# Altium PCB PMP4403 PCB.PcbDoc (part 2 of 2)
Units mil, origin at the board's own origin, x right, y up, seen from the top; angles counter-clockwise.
Board outline 2204 x 1635 mil, 2 copper layers (Top Layer, Bottom Layer), stack 62 mil thick; 78 components, 89 nets, 246 pads, 22 vias.
Unrouted connection lines stored in the file: 1.
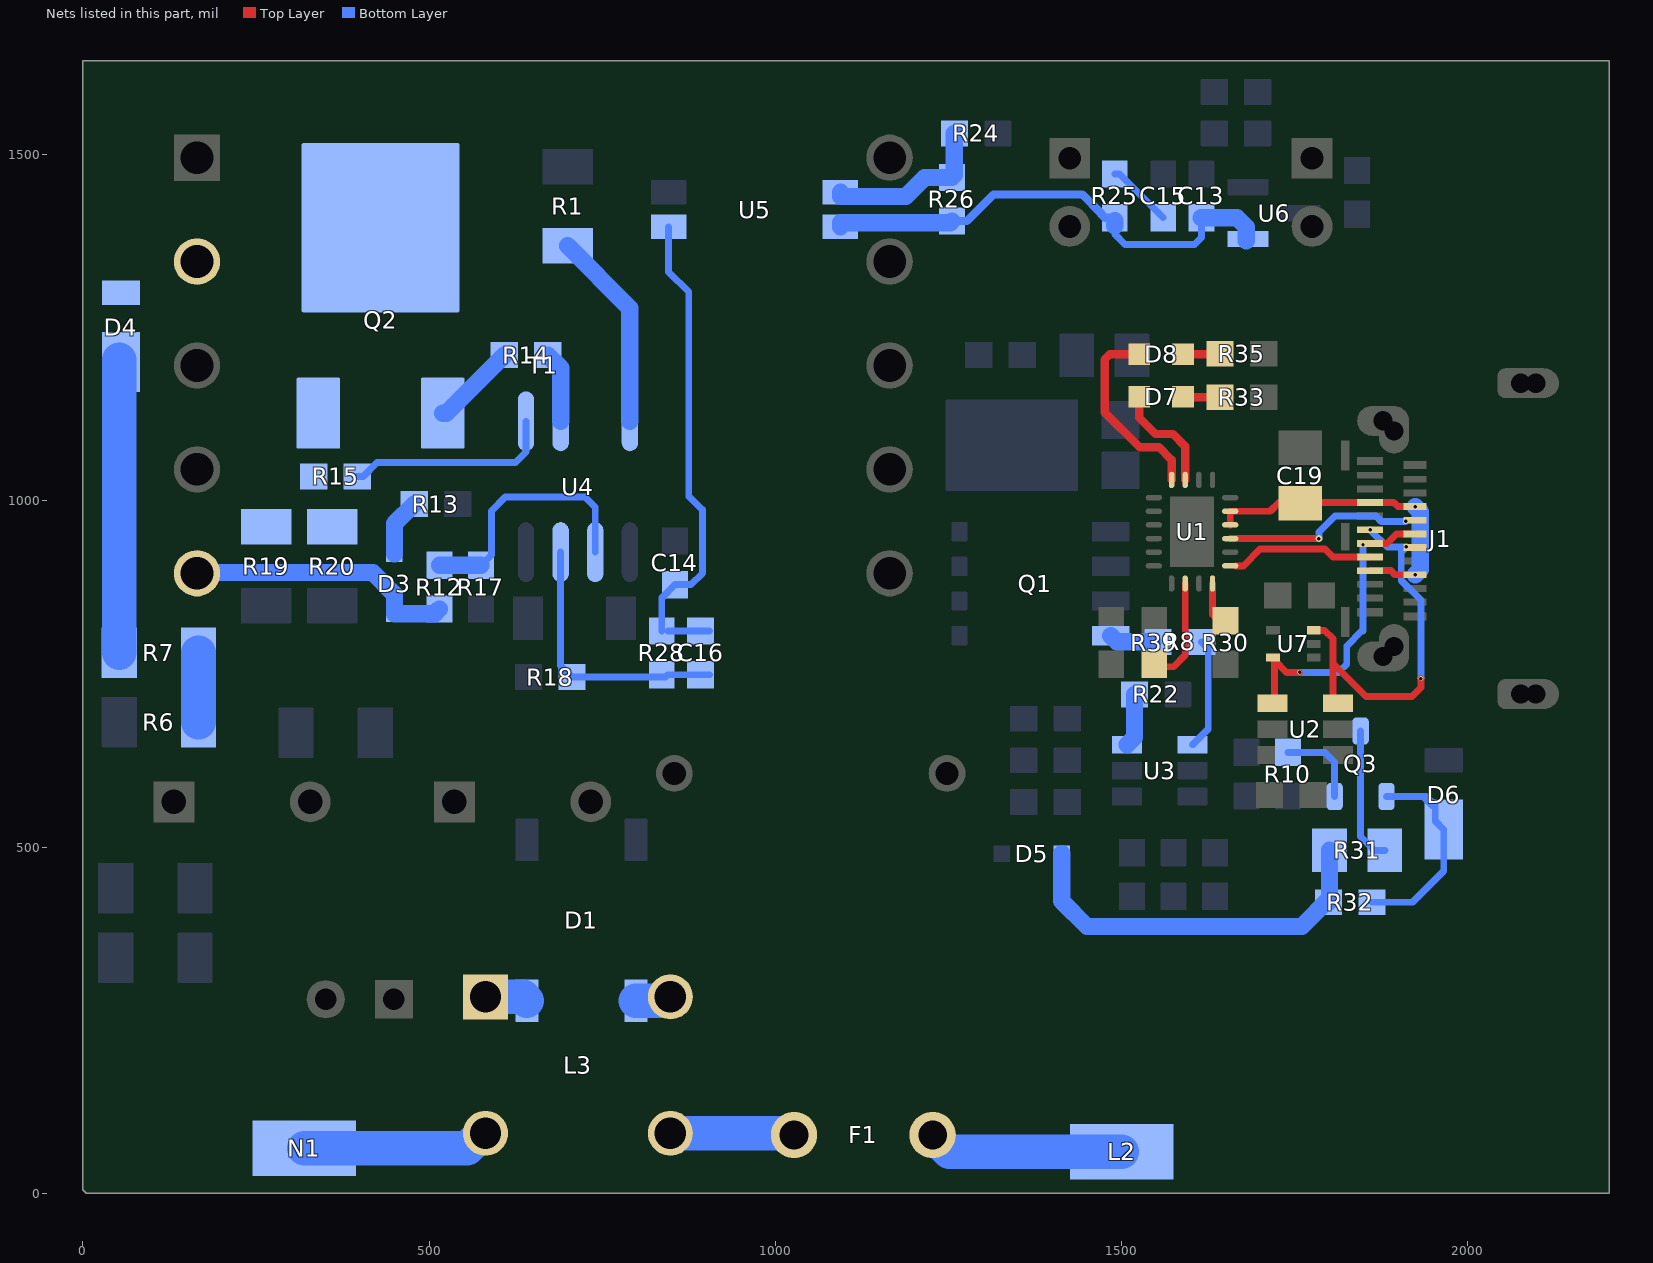
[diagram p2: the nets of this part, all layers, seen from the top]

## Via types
v1: diameter 10, hole 5, Top Layer to Bottom Layer, 8 vias
v2: diameter 7, hole 5, Top Layer to Bottom Layer, 8 vias
v3: diameter 19.68, hole 7.87, Top Layer to Bottom Layer, 6 vias

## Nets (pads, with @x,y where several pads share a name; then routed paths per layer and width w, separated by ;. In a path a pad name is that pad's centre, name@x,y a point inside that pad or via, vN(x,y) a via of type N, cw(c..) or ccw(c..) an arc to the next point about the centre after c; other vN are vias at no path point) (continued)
NetC13_2: C13.2 R25.1 R26.1 U5.2 U6.1 | length 706.8
  Bottom Layer w10: R25.1@1490.02,1397.17 1490.02,1385.42 1505.02,1370.42 1605.02,1370.42 1615.02,1380.42 C13.2@1615.02,1408.93
  Bottom Layer w12: R26.1@1255.02,1403.93 1276.52,1403.93 1315.02,1442.42 1443.19,1442.42 1470.54,1415.07 1470.54,1413.89 1475.51,1408.93 R25.1@1490.02,1408.93
  Bottom Layer w25: U5.2@1094.03,1395.42 1094.03,1401.39 1252.48,1401.39 R26.1@1255.02,1403.93 ; R25.1@1490.02,1397.17 R25.1@1490.02,1404.22 ; C13.2@1615.02,1408.93 1666.51,1408.93 1680.02,1395.42 U6.1@1680.02,1375.42
NetC14_2: C14.2 C16.1 R28.2 U5.3 | length 702.6
  Bottom Layer w10: R28.2@836.02,811.92 836.02,859.93 C14.2@855.02,878.93 878.52,878.93 895.02,895.42 895.02,987.42 894.02,987.42 875.02,1006.42 875.02,1301.41 846,1330.42 U5.3@846,1395.42 ; R28.2@845.02,811.92 C16.1@905.02,811.92
NetC15_2: C15.2 R25.2 | length 96.1
  Bottom Layer w10: R25.2@1490.02,1471.92 1497.02,1471.92 C15.2@1560.02,1408.93
NetC16_2: C16.2 R18.2 R28.1 U4.3 | length 387.3
  Bottom Layer w10: U4.3@690.02,925.93 690.02,761.92 R18.2@706.51,745.42 841.51,745.42 845.02,748.93 C16.2@905.02,748.93
NetC19_1: C19.1 J1.A4 J1.A9 J1.B4 J1.B9 U1.14 U1.15 | length 465.5
  Top Layer w10: U1.14@1656.79,965.26 U1.15@1656.79,984.63 ; U1.15@1656.79,984.95 1714.54,984.95 1727.18,997.59 J1.A9@1858.76,997.59 1892.85,997.59 1898.76,991.68 J1.B4@1923.72,991.68 ; J1.A4@1858.76,899.16 1888.76,899.16 1894.66,893.26 v2(1923.72,893.26)
  Bottom Layer w25: v2(1923.72,893.26) 1931.02,900.56 1931.02,984.42 v2(1924.02,991.42)
NetD1_3: D1.3 L3.4 | length 52.1
  Bottom Layer w50: D1.3@798.76,278.28 842.87,278.28 L3.4@848.52,283.92
NetD1_4: D1.4 L3.1 | length 62.1
  Bottom Layer w50: L3.1@581.52,283.92 635.63,283.92 D1.4@641.28,278.28
NetD3_1: D3.1 R13.2 | length 83.5
  Bottom Layer w25: D3.1@450.02,923.73 450.02,966.92 R13.2@478.52,995.42
NetD3_2: D3.2 R12.2 T1.5 | length 395
  Bottom Layer w25: T1.5@165.02,895.42 165.02,896.43 419.01,896.43 450.02,865.42 D3.2@450.02,837.11 508.2,837.11 R12.2@515.02,843.93
NetD4_1: D4.1 R7.1 | length 422.9
  Bottom Layer w50: R7.1@52.93,780.42 D4.1@52.93,1203.33
NetD4_2: D4.2 Q2.4 T1.2
NetD5_1: D5.1 R31.2 R32.2 | length 562.4
  Bottom Layer w25: D5.1@1413.32,490.42 1413.32,422.11 1450.02,385.42 1760.02,385.42 R32.2@1800.02,425.42 ; R32.2@1798.52,420.42 1800.02,421.92 R32.2@1800.02,425.42 ; R31.2@1800.02,495.42 R32.2@1800.02,425.42
NetD6_1: D6.1 Q3.1 R32.1 | length 321
  Bottom Layer w10: R32.1@1861.51,420.42 1920.21,420.42 1965.02,465.22 D6.1@1965.02,525.22 1952.77,537.47 D6.1@1952.77,560.42 ; Q3.1@1882.42,573.18 1935.02,573.18 ; 1935.02,573.18 1940.02,573.18 D6.1@1952.77,560.42 ; 1935.02,573.18 1947.77,560.42 D6.1@1952.77,560.42
NetD7_1: D7.1 U1.19 | length 162.3
  Top Layer w12: D7.1@1525.52,1150.42 1525.52,1119.92 1549.02,1096.42 1574.02,1096.42 1591.83,1078.61 1591.83,1056.42 U1.19@1591.83,1030.22
NetD7_2: D7.2 R33.1 | length 54
  Top Layer w12: D7.2@1588.51,1150.42 1589.31,1149.63 R33.1@1642.17,1149.63
NetD8_1: D8.1 U1.20 | length 283.3
  Top Layer w12: D8.1@1525.52,1211.69 1483.29,1211.69 1475.52,1203.92 1475.52,1127.92 1526.02,1077.42 1554.02,1077.42 1572.14,1059.3 U1.20@1572.14,1030.22
NetD8_2: D8.2 R35.1 | length 54
  Top Layer w12: D8.2@1588.51,1211.69 1641.44,1211.69 R35.1@1642.17,1212.42
NetF1_1: F1.1 L3.3 | length 181.7
  Bottom Layer w50: L3.3@848.52,86.92 1024.52,86.92 F1.1@1027.02,84.42 ; L3.3@848.52,91.92 L3.3@850.02,90.42
NetF1_2: F1.2 L2.1 | length 282.9
  Bottom Layer w50: F1.2@1227.02,84.42 1251.02,60.42 L2.1@1500.02,60.42
NetJ1_A5: J1.A5 U1.11 | length 208.5
  Top Layer w10: U1.11@1665.39,905.89 1665.39,906.21 1675.8,906.21 1700.02,930.42 1793.8,930.42 1805.37,918.85 J1.A5@1858.76,918.85
NetJ1_A6: J1.A6 J1.B6 U2.1 U7.5 | length 433.3
  Top Layer w10: U2.1@1717.77,707.82 1720.49,710.54 1720.49,769.95 1738.02,752.42 v2(1757.02,752.42) ; J1.A6@1858.76,938.53 1883.13,938.53 1896.91,952.31 J1.B6@1923.72,952.31
  Bottom Layer w10: v2(1757.02,752.42) 1813.02,752.42 ; 1814.02,753.42 1825.06,764.46 1825.06,790.41 1846.53,811.88 1848.47,811.88 v2(1848.47,936.88) v2@1849.02,937.42
NetJ1_A7: J1.A7 J1.B7 U2.6 U7.3 | length 574.5
  Top Layer w10: U7.3@1777.54,813.11 1793.02,813.11 1805.02,801.11 1805.02,765.42 ; U2.6@1797.26,707.82 1805.02,715.58 1805.02,765.42 ; v2(1911.02,933.42) 1911.81,932.63 J1.B7@1923.72,932.63 ; v2(1932.02,743.42) 1932.02,730.42 1919.02,717.42 1853.02,717.42 1805.02,765.42
  Bottom Layer w10: v1(1858.76,958.22) 1883.55,933.42 v2(1911.02,933.42) 1903.72,926.12 1903.72,884.97 1932.02,856.67 v2(1932.02,743.42)
NetJ1_B5: J1.B5 U1.13 | length 275.9
  Top Layer w10: U1.13@1656.79,945.58 v1(1784.86,945.58) v1@1785.02,945.42
  Bottom Layer w10: v1(1784.86,945.58) 1784.86,955.26 1807.81,978.22 1867.04,978.22 1874.84,970.42 v2(1910.02,970.42)
NetL3_2: L3.2 N1.1 | length 272.5
  Bottom Layer w50: N1.1@320.02,65.42 555.02,65.42 L3.2@581.52,91.92
NetQ1_4: Q1.4 R8.1 | length 71.9
  Bottom Layer w10: R8.1@1545.02,796.42 R8.1@1552.52,796.42
  Bottom Layer w25: Q1.4@1484.32,805.42 1493.32,796.42 R8.1@1545.02,796.42
NetQ2_1: Q2.1 R14.2 | length 123.5
  Bottom Layer w25: Q2.1@519.78,1126.56 524.66,1126.56 R14.2@608.52,1210.42
NetQ2_3: Q2.3 R15.2 R19.2 R20.2
NetQ3_2: Q3.2 R10.2 | length 123.1
  Bottom Layer w10: R10.2@1740.02,636.92 1793.52,636.92 1807.61,622.82 Q3.2@1807.61,573.18
NetQ3_3: Q3.3 R31.1 | length 195.5
  Bottom Layer w10: Q3.3@1845.02,667.67 1845.02,515.42 1865.02,495.42 R31.1@1880.02,495.42
NetR1_1: R1.1 U4.8 | length 290.7
  Bottom Layer w25: R1.1@700.02,1368.33 790.02,1278.33 U4.8@790.02,1114.91
NetR6_1: R6.1 R7.2 | length 100
  Bottom Layer w50: R6.1@167.1,680.42 R7.2@167.1,780.42
NetR8_2: R8.2 U3.4 | length 162
  Bottom Layer w10: U3.4@1602.26,647.82 1625.02,670.58 1625.02,786.92 R8.2@1615.51,796.42
NetR12_1: R12.1 R17.2 U4.2 | length 373.7
  Bottom Layer w10: R17.2@575.02,906.92 590.02,921.92 590.02,985.42 610.02,1005.42 725.02,1005.42 740.02,990.42 U4.2@740.02,925.93
  Bottom Layer w25: R12.1@515.02,906.92 R17.2@575.02,906.92
NetR14_1: R14.1 U4.6 | length 103.2
  Bottom Layer w25: R14.1@671.51,1210.42 690.02,1191.92 U4.6@690.02,1114.91
NetR15_1: R15.1 U4.5 | length 302.5
  Bottom Layer w10: R15.1@396.51,1035.42 405.02,1035.42 425.02,1055.42 625.02,1055.42 640.02,1070.42 U4.5@640.02,1114.91
NetR22_2: R22.2 U3.3 | length 77.1
  Bottom Layer w25: U3.3@1507.77,647.82 1518.52,658.57 R22.2@1518.52,720.42
NetR24_1: R24.1 R26.2 U5.1 | length 241.8
  Bottom Layer w10: R26.2@1255.02,1466.92 R26.2@1255.02,1470.42
  Bottom Layer w25: U5.1@1094.03,1445.42 1094.03,1439.46 1188.2,1439.46 1215.66,1466.92 R26.2@1255.02,1466.92 ; R26.2@1258.52,1470.42 R24.1@1258.52,1530.42
NetR30_2: R30.2 U1.10 | length 57.4
  Top Layer w10: U1.10@1631.2,880.62 1631.2,835.74 R30.2@1640.02,826.92
NetR39_1: R39.1 U1.8 | length 156.6
  Top Layer w10: R39.1@1547.07,763.93 1550.57,760.42 1575.02,760.42 1591.83,777.23 U1.8@1591.83,880.62
PWRGND: 
pads on no net: J1.A2 J1.A3 J1.A8 J1.A10 J1.A11 J1.B2 J1.B3 J1.B8 J1.B10 J1.B11 T1.3 T1.6 U1.1 U1.16 U1.17 U1.18 U2.3 U2.4 U7.2

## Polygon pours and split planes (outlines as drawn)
GND on Bottom Layer "Top Layer-No Net" (solid, remove dead copper, pour order 19): 1447.31,831.45 1450.02,834.15 1450.02,1165.42 1470.02,1185.42 1470.02,1243.42 1463.02,1250.42 1395.02,1250.42 1340.02,1250.42 1340.02,1305.42 1340.02,1405.42 1340.02,1410.42 1350.02,1420.42 1445.02,1420.42 1450.02,1420.42 1460.02,1410.42 1465.02,1405.42 1465.02,1370.42 1465.02,1365.42 1730.02,1365.42 1730.02,1410.42 1730.02,1415.42 1735.02,1420.42 1760.02,1445.42 2180.02,1445.42 2190.02,1445.42 2215.02,1420.42 2215.02,637.42 2168.02,590.42 1688.34,590.42 1640.02,638.74 1640.02,830.42 1455.02,830.42
NetC7_2 on Bottom Layer "Top Layer-No Net" (solid, remove dead copper, pour order 18): 1120.02,1015.42 1120.02,1250.42 1120.02,1255.42 1130.02,1265.42 1135.02,1270.42 1305.02,1270.42 1315.02,1270.42 1325.02,1260.42 1330.02,1255.42 1330.02,1175.42 1330.02,1170.42 1340.02,1160.42 1445.02,1160.42 1450.02,1155.42 1455.02,1150.42 1455.02,785.42 1455.02,780.42 1450.02,775.42 1445.02,770.42 1170.02,770.42 1145.02,770.42 1120.02,795.42
NetD4_2 on Bottom Layer "Top Layer-No Net" (solid, remove dead copper, pour order 13): 20.02,1270.42 20.02,1415.42 20.02,1420.42 30.02,1430.42 35.02,1435.42 240.02,1435.42 255.02,1450.42 265.02,1460.42 265.02,1535.42 280.02,1550.42 285.02,1555.42 570.02,1555.42 575.02,1550.42 575.02,1300.42 575.02,1280.42 555.02,1260.42 35.02,1260.42
NetQ2_3 on Bottom Layer "Top Layer-No Net" (solid, remove dead copper, pour order 12): 220.02,925.42 220.02,1130.42 220.02,1140.42 220.02,1195.42 375.02,1195.42 390.02,1195.42 390.02,1180.42 390.02,1080.42 390.02,1075.42 380.02,1065.42 370.02,1065.42 365.02,1060.42 365.02,1010.42 365.02,1005.42 370.02,1000.42 410.02,1000.42 415.02,995.42 415.02,920.42 415.02,915.42 410.02,910.42 405.02,905.42 235.02,905.42
GND on Top Layer "Top Layer-No Net" (solid, remove dead copper, pour order 16): 1712.02,1047.42 1712.02,1117.42 1712.02,1118.42 1714.02,1120.42 1716.02,1122.42 1762.02,1122.42 1797.02,1157.42 1917.02,1157.42 1933.02,1157.42 1945.02,1145.42 1945.02,1053.42 1945.02,1048.42 1942.02,1045.42 1941.02,1046.42 1840.02,1046.42 1840.02,1045.42 1831.02,1036.42 1720.02,1036.42
NetC19_1 on Top Layer "Top Layer-No Net" (solid, remove dead copper, pour order 22): 1640.02,965.42 1640.02,985.42 1650.02,995.42 1680.02,995.42 1690.02,1005.42 1700.02,1015.42 1713.02,1028.42 1771.02,1028.42 1817.02,1028.42 1830.02,1015.42 1840.02,1005.42 1840.02,995.42 1800.02,955.42 1710.02,955.42 1650.02,955.42
GND on Top Layer "Top Layer-No Net" (solid, remove dead copper, pour order 21): 1210.02,535.42 1210.02,765.42 1210.02,770.42 1230.02,790.42 1465.02,790.42 1480.02,790.42 2140.89,790.42 2153.02,781.12 2153.02,579.42 2153.02,430.38 2142.32,420.42 2075.02,420.42 1218.02,420.42 1210.02,428.42
NetC4_1 on Top Layer "Top Layer-No Net" (solid, remove dead copper, pour order 20): 1532.79,795.42 1580.02,795.42 1585.02,800.42 1585.02,895.42 1580.02,900.42 1570.02,900.42 1565.02,905.42 1560.02,910.42 1560.02,990.42 1461.02,1089.43 1461.02,1232.42 1477.02,1248.42 1673.02,1248.42 1673.02,1124.42 1751.02,1124.42 1751.02,1248.42 1928.02,1248.42 1965.02,1285.42 1965.02,1340.42 1965.02,1592.42 1937.02,1620.42 1650.02,1620.42 1142.02,1620.42 1130.02,1608.42 1130.02,1260.42 1142.02,1248.42 1205.02,1248.42 1210.02,1243.42 1210.02,1223.99 1210.02,795.42
GND on Top Layer "Top Layer-No Net" (solid, remove dead copper, pour order 15): 115.02,715.42 115.02,1105.42 125.02,1115.42 235.02,1115.42 260.02,1115.42 275.02,1130.42 290.02,1145.42 290.02,1410.42 290.02,1420.42 330.02,1460.42 335.02,1465.42 760.02,1465.42 854.02,1465.42 895.02,1424.42 895.02,555.42 895.02,468.42 867.02,440.42 325.02,440.42 280.02,440.42 265.02,455.42 265.02,465.42 265.02,640.42 265.02,645.42 240.02,670.42 170.02,670.42 160.02,670.42
NetC1_1 on Top Layer "Top Layer-No Net" (solid, remove dead copper, pour order 14): 25.02,490.42 20.02,495.42 20.02,1550.42 220.02,1550.42 225.02,1545.42 225.02,1455.42 225.02,1450.42 215.02,1440.42 210.02,1435.42 115.02,1435.42 100.02,1435.42 85.02,1420.42 75.02,1410.42 75.02,650.42 75.02,640.42 105.02,610.42 175.02,610.42 185.02,600.42 185.02,490.42 185.02,485.42 175.02,475.42 45.02,475.42
GND on Top Layer "Top Layer-No Net" (solid, remove dead copper, pour order 17): 1839.02,745.42 1811.02,773.42 1811.02,775.42 1811.02,841.42 1819.02,849.42 1823.48,853.89 1923.72,853.89 1937.55,853.89 1945.02,846.42 1949.47,841.97 1949.47,758.61 1949.47,738.87 1941.02,730.42 1940.02,731.42 1852.02,731.42

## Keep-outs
Keep-Out Layer:
  the board outline again, w10
  text ".Layer_Name" at 577,-858.49 h60

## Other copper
Top Layer:
  text ".Layer_Name" at 577,-858.49 h60
Bottom Layer:
  text ".Layer_Name" at 577,-858.49 h60

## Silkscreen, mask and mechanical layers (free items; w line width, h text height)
Top Overlay:
  text "PMP4403_RevA" at 1427.02,187.42 h60
  text ".Layer_Name" at 577,-858.49 h60
Bottom Overlay:
  text ".Layer_Name" at 577,-858.49 h60
Top Paste:
  text ".Layer_Name" at 577,-858.49 h60
Bottom Paste:
  text ".Layer_Name" at 577,-858.49 h60
Top Solder:
  text ".Layer_Name" at 577,-858.49 h60
  text ".Layer_Name" at 577,-858.49 h60
Bottom Solder:
  text ".Layer_Name" at 577,-858.49 h60
Drill Guide:
  text ".Layer_Name" at 577,-858.49 h60
M1 Board Outline:
  text ".Layer_Name" at 577,-858.49 h60
M2 Board Dimensions:
  rectangle: 125,-400 500,-275
  rectangle: 0,-275 125,-150
  lines w7: 0,-275 1000,-275 ; 0,-150 0,-400 1000,-400 1000,-150 ; 125,-400 125,-150 ; 250,-400 250,-150 ; 500,-400 500,-150 ; 750,-400 750,-150
  text ".Layer_Name" at 577,-858.49 h60
M3 3D STEP Top:
  text ".Layer_Name" at 577,-858.49 h60
M4 3D STEP Bottom:
  text ".Layer_Name" at 577,-858.49 h60
M5 Assembly Top:
  lines w10: -292,-930.17 6308,-930.17 ; -292,-726.83 6310,-726.83 ; -292,-523.5 -292,-1133.5 3713,-1133.5 6310,-1133.5 6310,-523.5 -291.5,-523.5 -291.5,-1133.5 1284,-1133.5 ; 2173,-1133.5 2173,-523.5 ; 3440,-726.83 3440,-523.5 ; 4280,-726.83 4280,-523.5 ; 4902,-1140 4902,-937.17
  text "COMPONENTS MARKED 'DNP' SHOULD NOT BE POPULATED." at 1153.5,-318.5 h60
  text "ASSEMBLY VARIANT:" at 1153,-434 h60
  text ".VariantName" at 2189,-434 h60
  text "PCB VIEWED FROM TOP SIDE" at -228.5,-655.67 h60
  text "BOARD #:" at 2248,-655.67 h60
  text ".PRJ_Number" at 2793.5,-655.67 h60
  text "REV:" at 3638,-655.67 h60
  text ".PCB_Rev" at 3929.5,-655.67 h60
  text "SVN REV:" at 4476,-655.67 h60
  text ".VersionControl_RevNumber" at 4982,-655.67 h60
  text "TID #:" at 2248,-859 h60
  text ".TID" at 2793.5,-859 h60
  text "PLOT NAME =" at -228.5,-1064.34 h60
  text ".plot_File_Name" at 577,-1064.34 h60
  text "GENERATED    :" at 2250,-1064.34 h60
  text ".Print_Date" at 3119.5,-1064.34 h60
  text ".Print_Time" at 3848.5,-1064.34 h60
  text "TEXAS INSTRUMENTS" at 5113,-1064.34 h60
M6 Assembly Bottom:
  lines w10: -292.5,-727.33 6309.5,-727.33 ; -290.5,-930.67 6309.5,-930.67 ; 1115.5,-1140.5 1115.5,-937.67 ; 1737.5,-727.33 1737.5,-524 ; 2577.5,-727.33 2577.5,-524 ; 3844.5,-1134 3844.5,-524 ; 4733.5,-1134 6309,-1134 6309,-524 -292.5,-524 -292.5,-1134 2304.5,-1134 6309.5,-1134 6309.5,-524
  text "COMPONENTS MARKED 'DNP' SHOULD NOT BE POPULATED." at 6102,-318 h60
  text ".VariantName" at 5058,-434 h60
  text "ASSEMBLY VARIANT:" at 6097,-434 h60
  text ".VersionControl_RevNumber" at 1035.5,-656.17 h60
  text "SVN REV:" at 1541.5,-656.17 h60
  text ".PCB_Rev" at 2088,-656.17 h60
  text "REV:" at 2379.5,-656.17 h60
  text ".PRJ_Number" at 3224,-656.17 h60
  text "BOARD #:" at 3769.5,-656.17 h60
  text "PCB VIEWED FROM BOTTOM SIDE" at 6246,-656.17 h60
  text ".TID" at 3224,-859.5 h60
  text "TID #:" at 3769.5,-859.5 h60
  text "TEXAS INSTRUMENTS" at 904.5,-1064.84 h60
  text ".Print_Time" at 2169,-1064.84 h60
  text ".Print_Date" at 2898,-1064.84 h60
  text "GENERATED    :" at 3767.5,-1064.84 h60
  text ".plot_File_Name" at 5440.5,-1064.84 h60
  text "PLOT NAME =" at 6246,-1064.84 h60
M9 Title Sheet:
  drawing of 57 lines, arcs and shapes, not listed
  text "1" at 739.84,8036.5 h70
  text "2" at 3235.5,8036.5 h70
  text "3" at 5724.84,8036.5 h70
  text "4" at 8231.51,8036.5 h70
  text "5" at 10730.5,8036.5 h70
  text "6" at 13235.5,8036.5 h70
  text "A" at -416.5,6893.5 h70
  text "A" at 14383.5,6893.5 h70
  text "B" at -416.5,4513.5 h70
  text "B" at 14383.5,4513.5 h70
  text "C" at -416.5,2138.5 h70
  text "C" at 14383.5,2138.5 h70
  text "PROJECT TITLE:" at 11343.5,277.5 h45
  text ".PRJ_Title" at 11393.5,144.17 h70
  text "DESIGNED FOR:" at 11343.5,-23.5 h45
  text ".PRJ_Customer" at 11393.5,-163.5 h70
  text "D" at -416.5,-231.5 h70
  text "D" at 14383.5,-231.5 h70
  text "FILE NAME:" at 11343.5,-323.5 h45
  text ".PCB_File_Name_No_Path" at 11393.5,-443.5 h70
  text "Texas Instruments (TI) and/or its licensors do not warrant the accuracy or completeness of this specification" at 6374,-605.34 h45
  text "ENGINEER:" at 11343.5,-613.5 h45
  text "LAYOUT BY:" at 12848.5,-613.5 h45
  text "or any information contained therein. TI and/or its licensors do not warrant that this design will meet" at 6329.01,-718 h45
  text ".PRJ_Engineer" at 11393.5,-768.49 h70
  text ".PCB_Layout" at 12899,-768.49 h70
  text "the specifications, will be suitable for your application or fit for any particular purpose, or will operate in" at 6329.01,-830.67 h45
  text ".Layer_Name" at 577,-858.49 h60
  text "ALTIUM DESIGNER VERSION:" at 12848.5,-923.5 h45
  text "an implementation. TI and/or its licensors do not warrant that the design is production worthy. You should" at 6329.01,-943.33 h45
  text "completely validate and test your design implementation to confirm the system functionality for your application." at 6374,-1056 h45
  text ".print_Scale" at 11393.5,-1056.83 h70
  text ".Application_BuildNumber" at 12899,-1056.83 h70
  text "1" at 739.84,-1263.5 h70
  text "2" at 3235.5,-1263.5 h70
  text "3" at 5724.84,-1263.5 h70
  text "4" at 8231.51,-1263.5 h70
  text "5" at 10730.5,-1263.5 h70
  text "6" at 13235.5,-1263.5 h70
M10 Fab Notes:
  drawing of 173 lines, arcs and shapes, not listed
  text "DESIGN INFORMATION" at 12377.02,6201 h60
  text "MIN. TRACK WIDTH:" at 11732.46,6021 h60
  text "8" at 12828.7,6021 h60
  text "MIL" at 12983.46,6021 h60
  text "MIN. CLEARANCE:" at 11732.46,5889 h60
  text "0.2" at 12768.7,5889 h60
  text "mm" at 12983.46,5889 h60
  text "MIN. VIA PAD SIZE:" at 11732.46,5757 h60
  text "24" at 12798.71,5757 h60
  text "MIL" at 12983.46,5757 h60
  text "0.05mm (2MIL)" at 12427.46,5615.29 h60
  text "MINIMUM ANNULAR RING" at 11403.23,5611 h60
  text "EXTERNAL" at 13135.46,5611 h60
  text "PER" at 11603.23,5493 h60
  text "IPC-D-275 CLASS 2 LEVEL C" at 11823.23,5493 h60
  text "MIL, HOLES" at 13311.46,5380.71 h60
  text "+/-" at 12919,5380 h60
  text "+/-" at 13773,5380 h60
  text "REGISTRATION TOLERANCES:" at 11403.23,5375 h60
  text "METAL" at 12603,5375 h60
  text "5" at 13179.2,5375 h60
  text "3" at 14012.2,5375 h60
  text "MIL" at 14128.46,5375 h60
  text "+/-" at 13773,5262 h60
  text "HOLE SIZE TOLERANCE (UNLESS OTHERWISE SPECIFIED):" at 11403.23,5257 h60
  text "3" at 14012.2,5257 h60
  text "MIL" at 14128.46,5257 h60
  text "MATERIAL:" at 11328.46,5047.54 h60
  text "FR-4 High Tg" at 12314.9,4907.21 h60
  text "FR-408" at 11749.46,4898.64 h60
  text "OTHER" at 13237.46,4898.64 h60
  text "X" at 12160,4895 h60
  text "62 MIL (1.6mm) +/-10%" at 12069.56,4735.92 h60
  text "THICKNESS:" at 11403.23,4731.64 h60
  text "X" at 11941.4,4731.64 h60
  text "OTHER" at 13354.46,4731.64 h60
  text "TOLERANCE:" at 11403.23,4573.64 h60
  text "X" at 12242.53,4573.64 h60
  text "ANSI IPC-6012 TYPE 3 CLASS 2" at 12429.48,4573.64 h60
  text "OTHER +/-" at 12429.46,4417.64 h60
  text "BOW & TWIST:" at 11403.23,4260.64 h60
  text "X" at 12242.53,4260.64 h60
  text "ANSI IPC-6012 TYPE 3 CLASS 2" at 12429.48,4260.64 h60
  text "OTHER +/-" at 12429.46,4102.13 h60
  text "DRILLING:" at 11328.46,3963.64 h60
  text "REFERENCE:" at 11403.23,3846.64 h60
  text "X" at 12051.46,3846.64 h60
  text "AS SHOWN" at 12238.46,3846.64 h60
  text "X" at 12952.46,3846.64 h60
  text "NC_DRILL FILES" at 13089.46,3846.64 h60
  text "PTH COPPER THICKNESS:" at 11403.23,3688.64 h60
  text "X" at 12533.46,3688.64 h60
  text "20-30 um" at 12670.46,3688.64 h60
  text "OTHER" at 13387.46,3688.64 h60
  text "BOARD FINISH:" at 11328.46,3529.64 h60
  text "SILKSCREEN:" at 11483.68,3411.64 h60
  text "X" at 12432.46,3411.64 h60
  text "TOP" at 12558.46,3411.64 h60
  text "X" at 12942.46,3411.64 h60
  text "BOTTOM" at 13069.46,3411.64 h60
  text "SILKSCREEN COLOR:" at 11483.68,3244.64 h60
  text "X" at 12431.42,3244.64 h60
  text "WHITE" at 12558.46,3244.64 h60
  text "OTHER" at 13069.46,3244.64 h60
  text "X" at 12562.42,3085.44 h60
  text "GREEN" at 12689.46,3085.44 h60
  text "OTHER" at 13307.46,3085.44 h60
  text "SOLDER RESIST COLOR:" at 11483.68,3074.64 h60
  text "X" at 12562.42,2915.44 h60
  text "MATTE" at 12689.46,2915.44 h60
  text "SEMI-GLOSS" at 13307,2914.8 h60
  text "IMMERSION GOLD (ENIG)" at 12389.46,2726.92 h60
  text "ENEPIG" at 13727,2723.64 h60
  text "SURFACE FINISH:" at 11328.46,2722.64 h60
  text "X" at 12202.51,2722.64 h60
  text "IMM. TIN/SILVER OR EQUIV" at 11658,2565.64 h60
  text "OTHER" at 13089.46,2565.64 h60
  text "ARRAY/PANEL:" at 11328.46,2386.64 h60
  text "CUT AND TRIM PER M1 BOARD OUTLINE" at 12389.46,2382.35 h60
  text "N.C. ROUTE" at 12389.46,2230.64 h60
  text "X" at 13068.46,2230.64 h60
  text "V. SCORE" at 13255.46,2230.64 h60
  text "CERTIFICATION:" at 11328.46,2093.64 h60
  text "MATERIALS AND WORKMANSHIP FOR ALL PCBS" at 12053.46,2093.64 h60
  text "TO MEET OR EXCEED THE REQUIREMENTS OF:" at 12053.46,1995.64 h60
  text "X" at 11679.96,1859.13 h60
  text "ANSI IPC-A-600F CLASS ->" at 11818.96,1859.13 h60
  text "X" at 13458.02,1859.13 h60
  text "2" at 13576.96,1859.14 h60
  text "1" at 13261.96,1857.64 h60
  text "3" at 13930.96,1857.64 h60
  text "X" at 12494.02,1699.64 h60
  text "RoHS" at 12630.96,1699.64 h60
  text "OTHER" at 13275.36,1699.64 h60
  text "PER ORDER" at 13672.42,1699.64 h60
  text "ALL BOARDS MUST MEET OR EXCEED UL94-V0 REQUIREMENTS." at 11356,1534 h60
  text "PCB MUST BEAR THE UL94V-0 UL REGISTERED MATERIAL ID NUMBER" at 11356,1414 h60
  text "ADDITIONAL REQUIREMENTS:" at 11328.46,1240.64 h60
  text "MICROSECTION:" at 11403.23,1125.64 h60
  text "YES" at 12308.96,1125.64 h60
  text "REQUIRED" at 13170.46,969.49 h60
  text "BARE BOARD ELEC. TEST:" at 11403.23,966.64 h60
  text "NONE" at 12708.96,966.64 h60
  text "X" at 13043.46,966.64 h60
  text "PER ORDER" at 13762.46,966.64 h60
  text ".Layer_Name" at 577,-858.49 h60
M11 Gerber Information:
  lines w10: -292,-930.17 6308,-930.17 ; -292,-726.83 6310,-726.83 ; -292,-523.5 -292,-1133.5 3713,-1133.5 6310,-1133.5 6310,-523.5 -291.5,-523.5 -291.5,-1133.5 1284,-1133.5 ; 2173,-1133.5 2173,-523.5 ; 3440,-726.83 3440,-523.5 ; 4280,-726.83 4280,-523.5 ; 4902,-1140 4902,-937.17
  text "ALL ARTWORK VIEWED FROM TOP SIDE" at -228.5,-655.67 h60
  text "BOARD #:" at 2248,-655.67 h60
  text ".PRJ_Number" at 2793.5,-655.67 h60
  text "REV:" at 3638,-655.67 h60
  text ".PCB_Rev" at 3929.5,-655.67 h60
  text "SVN REV:" at 4476,-655.67 h60
  text ".VersionControl_RevNumber" at 4982,-655.67 h60
  text "LAYER NAME =" at -228.5,-858.49 h60
  text "TID #:" at 2248,-859 h60
  text ".TID" at 2793.5,-859 h60
  text "PLOT NAME =" at -228.5,-1064.34 h60
  text ".plot_File_Name" at 577,-1064.34 h60
  text "GENERATED    :" at 2250,-1064.34 h60
  text ".Print_Date" at 3119.5,-1064.34 h60
  text ".Print_Time" at 3848.5,-1064.34 h60
  text "TEXAS INSTRUMENTS" at 5113,-1064.34 h60
M12 Stackup:
  drawing of 191 lines, arcs and shapes, not listed
  text "Layer" at 9790.58,7830 h60
  text "Name" at 10200.49,7830 h60
  text "Material" at 11130.23,7830 h60
  text "Thickness" at 11990,7830 h60
  text "Constant" at 12639.84,7830 h60
  text "Board Layer Stack" at 13209.7,7830 h60
  text "1" at 9790.58,7710 h60
  text "Top Overlay" at 10200.49,7710 h60
  text "2" at 9790.58,7590 h60
  text "Top Solder" at 10200.49,7590 h60
  text "Solder Resist" at 11130.23,7590 h60
  text "0.40mil" at 11990,7590 h60
  text "3.5" at 12639.84,7590 h60
  text "3" at 9790.58,7470 h60
  text "Top Layer" at 10200.49,7470 h60
  text "Copper" at 11130.23,7470 h60
  text "1.40mil" at 11990,7470 h60
  text "4" at 9790.58,7350 h60
  text "Dielectric1" at 10200.49,7350 h60
  text "FR-4" at 11130.23,7350 h60
  text "59.20mil" at 11990,7350 h60
  text "4.8" at 12639.84,7350 h60
  text "5" at 9790.58,7230 h60
  text "Bottom Layer" at 10200.49,7230 h60
  text "Copper" at 11130.23,7230 h60
  text "1.40mil" at 11990,7230 h60
  text "6" at 9790.58,7110 h60
  text "Bottom Solder" at 10200.49,7110 h60
  text "Solder Resist" at 11130.23,7110 h60
  text "0.40mil" at 11990,7110 h60
  text "3.5" at 12639.84,7110 h60
  text "7" at 9790.58,6990 h60
  text "Bottom Overlay" at 10200.49,6990 h60
  text ".Layer_Name" at 577,-858.49 h60
M13 Component Bodies Top:
  text ".Layer_Name" at 577,-858.49 h60
M14 Component Bodies Bottom:
  text ".Layer_Name" at 577,-858.49 h60
M15 Courtyards Top:
  text ".Layer_Name" at 577,-858.49 h60
M16 Courtyards Bottom:
  text ".Layer_Name" at 577,-858.49 h60
Drill Drawing:
  text ".Layer_Name" at 577,-858.49 h60

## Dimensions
0,-400 to 1000,-400 on M2 Board Dimensions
